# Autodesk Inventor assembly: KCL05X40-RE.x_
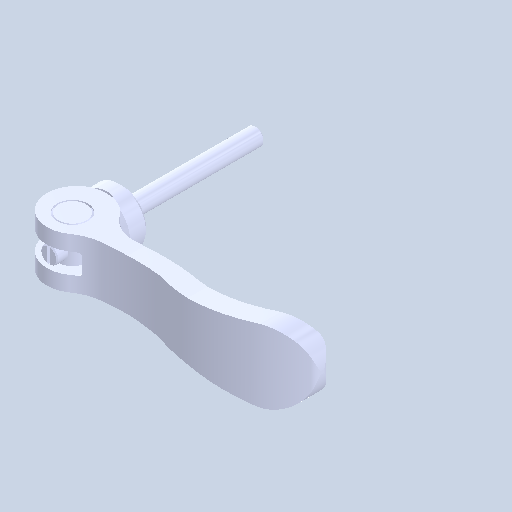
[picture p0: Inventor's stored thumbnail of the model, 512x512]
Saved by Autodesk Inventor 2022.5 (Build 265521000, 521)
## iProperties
Created: 2024-08
Part Number: KCL05X40-RE.x_
Document SubType Name: Assembly
Designer: ImaoCorp
Author: ImaoCorp
Sending System: SOLIDWORKS 2022-2022290
MC: AMD64
MC_MODEL: Intel64 Family 6 Model 60 Stepping 3, GenuineIntel
OS: Windows_NT
FRU: Parasolid Version 33.1, build 260,  4-25-2022
FORMAT: text
GUISE: transmit
KEY: FILEKCL05X40-RE.x_t
DATE: Thu Aug 29 10:49:14 2024
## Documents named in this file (5)
- Y:\5.更新分\2024年対応\1001_KCL\データ\kcl05x40-re\KCL05X40-RE.x_.iam
- Y:\5.更新分\2024年対応\1001_KCL\データ\kcl05x40-re\KCL05X40-RE_01.ipt
- Y:\5.更新分\2024年対応\1001_KCL\データ\kcl05x40-re\KCL05X40-RE_02.ipt
- Y:\5.更新分\2024年対応\1001_KCL\データ\kcl05x40-re\KCL05X40-RE_03.ipt
- Y:\5.更新分\2024年対応\1001_KCL\データ\kcl05x40-re\KCL05X40-RE_04.ipt
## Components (4 placed, 4 different names)
1. KCL05X40-RE_01
2. KCL05X40-RE_02
3. KCL05X40-RE_03
4. KCL05X40-RE_04
